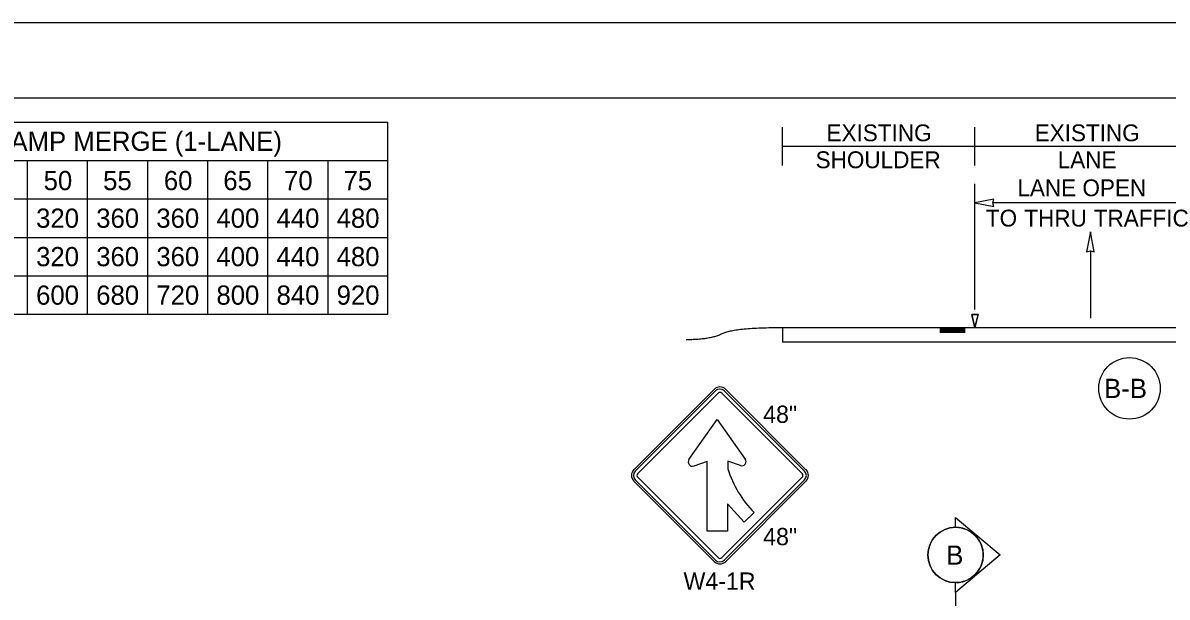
# Model space of a CAD drawing. Extents: x 99999 to 100116, y 99995 to 100013.
# Drawn here: x 100048.01 to 100052.769, y 100008.298 to 100010.687 of the extents above; entities that cross this region are included whole.
import ezdxf

# ---------------------------------------------------------------- set-up
doc = ezdxf.new("R2010")
doc.units = 0
for name, color, linetype in [('SH_GI_PlotLimits', 7, 'Continuous'), ('SH_GI_SectionCut', 7, 'Continuous'), ('SH_GI_SheetBorder', 7, 'Continuous'), ('SH_TI_Tables', 7, 'Continuous'), ('TR_SN_ConstructionSigns', 7, 'Continuous'), ('TR_WZ_ArrowLeftStrRightTurn', 7, 'Continuous'), ('TR_WZ_WorkZoneDetails', 7, 'Continuous')]:
    doc.layers.add(name, color=color, linetype=linetype)

msp = doc.modelspace()

# ---------------------------------------------------------------- linework, layer by layer
at = {"layer": 'SH_GI_PlotLimits'}
msp.add_lwpolyline([(100039.0625, 99999.6875), (100056.0625, 99999.6875), (100056.0625, 100010.6875), (100039.0625, 100010.6875)], close=True, dxfattribs=at)
at = {"layer": 'SH_GI_SectionCut'}
for p, q in [((100051.8894, 100008.589), (100051.8894, 100008.6297)), ((100051.8894, 100008.6297), (100052.0755, 100008.4738)), ((100052.0755, 100008.4738), (100051.8894, 100008.3179)), ((100051.8894, 100008.3179), (100051.8894, 100008.3586)), ((100051.8894, 100008.3179), (100051.8894, 100006.8828))]:
    msp.add_line(p, q, dxfattribs=at)
msp.add_circle((100051.8894, 100008.4738), 0.1152, dxfattribs=at)
msp.add_circle((100051.8894, 100008.4738), 0.1152, dxfattribs=at)
for start, end in [(90.0022, 269.9978), (269.9978, 90.0022), (269.9978, 90.0022)]:
    msp.add_arc((100051.8894, 100008.4738), 0.1152, start, end, dxfattribs=at)
at = {"layer": 'SH_GI_SheetBorder'}
msp.add_line((100040, 100010.375), (100055.75, 100010.375), dxfattribs=at)
at = {"layer": 'SH_TI_Tables'}
for p, q in [((100046.2222, 100010.275), (100049.5278, 100010.275)), ((100049.5278, 100009.475), (100049.5278, 100010.275)), ((100046.2222, 100010.115), (100049.5278, 100010.115)), ((100048.0278, 100010.115), (100048.0278, 100009.795)), ((100048.2778, 100010.115), (100048.2778, 100009.795)), ((100048.5278, 100010.115), (100048.5278, 100009.795)), ((100048.7778, 100010.115), (100048.7778, 100009.795)), ((100049.0278, 100010.115), (100049.0278, 100009.795)), ((100049.2778, 100010.115), (100049.2778, 100009.795)), ((100046.2222, 100009.955), (100048.0278, 100009.955)), ((100048.0278, 100009.955), (100049.5278, 100009.955)), ((100046.2222, 100009.795), (100048.0278, 100009.795)), ((100048.0278, 100009.795), (100049.5278, 100009.795)), ((100048.0278, 100009.795), (100048.0278, 100009.635)), ((100048.2778, 100009.795), (100048.2778, 100009.635)), ((100048.5278, 100009.795), (100048.5278, 100009.635)), ((100048.7778, 100009.795), (100048.7778, 100009.635)), ((100049.0278, 100009.795), (100049.0278, 100009.635)), ((100049.2778, 100009.795), (100049.2778, 100009.635)), ((100046.2222, 100009.635), (100048.0278, 100009.635)), ((100048.0278, 100009.635), (100049.5278, 100009.635)), ((100048.0278, 100009.635), (100048.0278, 100009.475)), ((100048.2778, 100009.635), (100048.2778, 100009.475)), ((100048.5278, 100009.635), (100048.5278, 100009.475)), ((100048.7778, 100009.635), (100048.7778, 100009.475)), ((100049.0278, 100009.635), (100049.0278, 100009.475)), ((100049.2778, 100009.635), (100049.2778, 100009.475)), ((100046.2222, 100009.475), (100048.0278, 100009.475)), ((100048.0278, 100009.475), (100049.5278, 100009.475))]:
    msp.add_line(p, q, dxfattribs=at)
at = {"layer": 'TR_SN_ConstructionSigns'}
for p, q in [((100050.8855, 100009.1627), (100050.5514, 100008.8286)), ((100050.8915, 100009.1568), (100050.5574, 100008.8227)), ((100051.2614, 100008.8227), (100050.9273, 100009.1568)), ((100051.2673, 100008.8286), (100050.9332, 100009.1627)), ((100050.5673, 100008.8127), (100050.9014, 100009.1468)), ((100050.9173, 100009.1468), (100051.2514, 100008.8127)), ((100050.7806, 100008.871), (100050.8984, 100009.0367)), ((100050.8984, 100009.0367), (100051.0149, 100008.8728)), ((100050.8557, 100008.8629), (100050.8009, 100008.8439)), ((100050.8557, 100008.5728), (100050.8557, 100008.8629)), ((100050.9945, 100008.8458), (100050.9426, 100008.8644)), ((100050.9426, 100008.8644), (100050.9426, 100008.832)), ((100050.5514, 100008.7809), (100050.8855, 100008.4468)), ((100050.5574, 100008.7869), (100050.8915, 100008.4528)), ((100050.9014, 100008.4627), (100050.5673, 100008.7968)), ((100051.2514, 100008.7968), (100050.9173, 100008.4627)), ((100050.9273, 100008.4528), (100051.2614, 100008.7869)), ((100050.9332, 100008.4468), (100051.2673, 100008.7809)), ((100051.0103, 100008.6097), (100050.9411, 100008.6862)), ((100050.9411, 100008.6862), (100050.9411, 100008.5728)), ((100051.0515, 100008.6509), (100051.0103, 100008.6097)), ((100050.9411, 100008.5728), (100050.8557, 100008.5728))]:
    msp.add_line(p, q, dxfattribs=at)
for centre, radius, start, end in [((100050.9094, 100009.1389), 0.0338, 45, 135), ((100050.9094, 100009.1389), 0.0253, 45, 135), ((100050.9094, 100009.1389), 0.0113, 45, 135), ((100050.795, 100008.8607), 0.0177, 144.5862, 289.1062), ((100051.0005, 100008.8626), 0.0177, 250.3331, 35.4138), ((100050.5753, 100008.8048), 0.0338, 135, 225), ((100050.5753, 100008.8048), 0.0253, 135, 225), ((100051.3557, 100008.9571), 0.4316, 196.843, 225.185), ((100051.2435, 100008.8048), 0.0253, 315, 45), ((100051.2435, 100008.8048), 0.0338, 315, 45), ((100050.5753, 100008.8048), 0.0113, 135, 225), ((100051.2435, 100008.8048), 0.0113, 315, 45), ((100050.9094, 100008.4707), 0.0338, 225, 315), ((100050.9094, 100008.4707), 0.0253, 225, 315), ((100050.9094, 100008.4707), 0.0113, 225, 315)]:
    msp.add_arc(centre, radius, start, end, dxfattribs=at)
at = {"layer": 'TR_WZ_ArrowLeftStrRightTurn'}
msp.add_line((100052.45, 100009.7386), (100052.45, 100009.4587), dxfattribs=at)
msp.add_lwpolyline([(100052.45, 100009.8187), (100052.4335, 100009.7347), (100052.45, 100009.7386), (100052.4665, 100009.7347)], close=True, dxfattribs=at)
at = {"layer": 'TR_WZ_WorkZoneDetails'}
for p, q in [((100051.17, 100010.094), (100051.17, 100010.254)), ((100051.97, 100010.094), (100051.97, 100010.254)), ((100051.17, 100010.174), (100051.97, 100010.174)), ((100051.97, 100010.174), (100052.93, 100010.174)), ((100051.97, 100009.4946), (100051.97, 100010.0183)), ((100052.855, 100009.9383), (100052.045, 100009.9383)), ((100055.65, 100009.4187), (100051.17, 100009.4187)), ((100051.17, 100009.4187), (100051.17, 100009.3587)), ((100051.8236, 100009.4146), (100051.93, 100009.4146)), ((100051.8236, 100009.4101), (100051.93, 100009.4101)), ((100051.8236, 100009.4055), (100051.93, 100009.4055)), ((100051.8236, 100009.4014), (100051.93, 100009.4014)), ((100055.65, 100009.3587), (100051.17, 100009.3587))]:
    msp.add_line(p, q, dxfattribs=at)
for points in [[(100051.97, 100009.9383), (100052.0486, 100009.9229), (100052.045, 100009.9383), (100052.0486, 100009.9537)], [(100051.97, 100009.4187), (100051.9566, 100009.4746), (100051.9833, 100009.4746)]]:
    msp.add_lwpolyline(points, close=True, dxfattribs=at)
msp.add_lwpolyline([(100051.9833, 100009.4746), (100051.9566, 100009.4746), (100051.97, 100009.4187), (100051.9833, 100009.4746)], dxfattribs=at)
msp.add_circle((100052.6128, 100009.1668), 0.128, dxfattribs=at)
msp.add_open_spline([(100051.17, 100009.4187), (100050.9691, 100009.4187), (100050.8687, 100009.369), (100050.7683, 100009.369)], degree=2, dxfattribs=at)

# ---------------------------------------------------------------- texts
at = {"layer": 'SH_GI_SectionCut'}
msp.add_text('B', height=0.08, rotation=0.01, dxfattribs=at).set_placement((100051.8507, 100008.4331))
at = {"layer": 'SH_TI_Tables'}
for s, p in [('PARALLEL TEMPORARY ON-RAMP MERGE (1-LANE)', (100046.4067, 100010.155)), ('50', (100048.0963, 100009.9915)), ('55', (100048.3437, 100009.9915)), ('60', (100048.5963, 100009.9915)), ('65', (100048.8437, 100009.9915)), ('70', (100049.0963, 100009.9915)), ('75', (100049.3437, 100009.9915)), ('320', (100048.065, 100009.835)), ('360', (100048.315, 100009.835)), ('360', (100048.565, 100009.835)), ('400', (100048.815, 100009.835)), ('440', (100049.065, 100009.835)), ('480', (100049.315, 100009.835)), ('320', (100048.065, 100009.675)), ('360', (100048.315, 100009.675)), ('360', (100048.565, 100009.675)), ('400', (100048.815, 100009.675)), ('440', (100049.065, 100009.675)), ('480', (100049.315, 100009.675)), ('600', (100048.065, 100009.515)), ('680', (100048.315, 100009.515)), ('720', (100048.565, 100009.515)), ('800', (100048.815, 100009.515)), ('840', (100049.065, 100009.515)), ('920', (100049.315, 100009.515))]:
    msp.add_text(s, height=0.08, rotation=360, dxfattribs=at).set_placement(p)
at = {"layer": 'TR_SN_ConstructionSigns'}
for s, p in [('48"', (100051.0892, 100009.0233)), ('48"', (100051.0892, 100008.5142)), ('W4-1R', (100050.7579, 100008.3289))]:
    msp.add_text(s, height=0.072, rotation=360, dxfattribs=at).set_placement(p)
at = {"layer": 'TR_WZ_WorkZoneDetails'}
for s, height, p in [('EXISTING', 0.07, (100051.3527, 100010.195)), ('EXISTING', 0.07, (100052.2185, 100010.195)), ('SHOULDER', 0.07, (100051.3073, 100010.083)), ('LANE', 0.07, (100052.3142, 100010.083)), ('LANE OPEN', 0.07, (100052.1466, 100009.9663)), ('TO', 0.07, (100052.0154, 100009.8403)), ('THRU', 0.07, (100052.1754, 100009.8403)), ('TRAFFIC', 0.07, (100052.4643, 100009.8403)), ('B-B', 0.08, (100052.5072, 100009.1268))]:
    msp.add_text(s, height=height, dxfattribs=at).set_placement(p)

doc.saveas('drawing.dxf')
